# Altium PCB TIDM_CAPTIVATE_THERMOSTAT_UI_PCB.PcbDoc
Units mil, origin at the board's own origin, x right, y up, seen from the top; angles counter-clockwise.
Board outline 2500 x 2500 mil, 2 copper layers (Top Layer, Bottom Layer), stack 62 mil thick; 61 components, 47 nets, 313 pads, 106 vias.
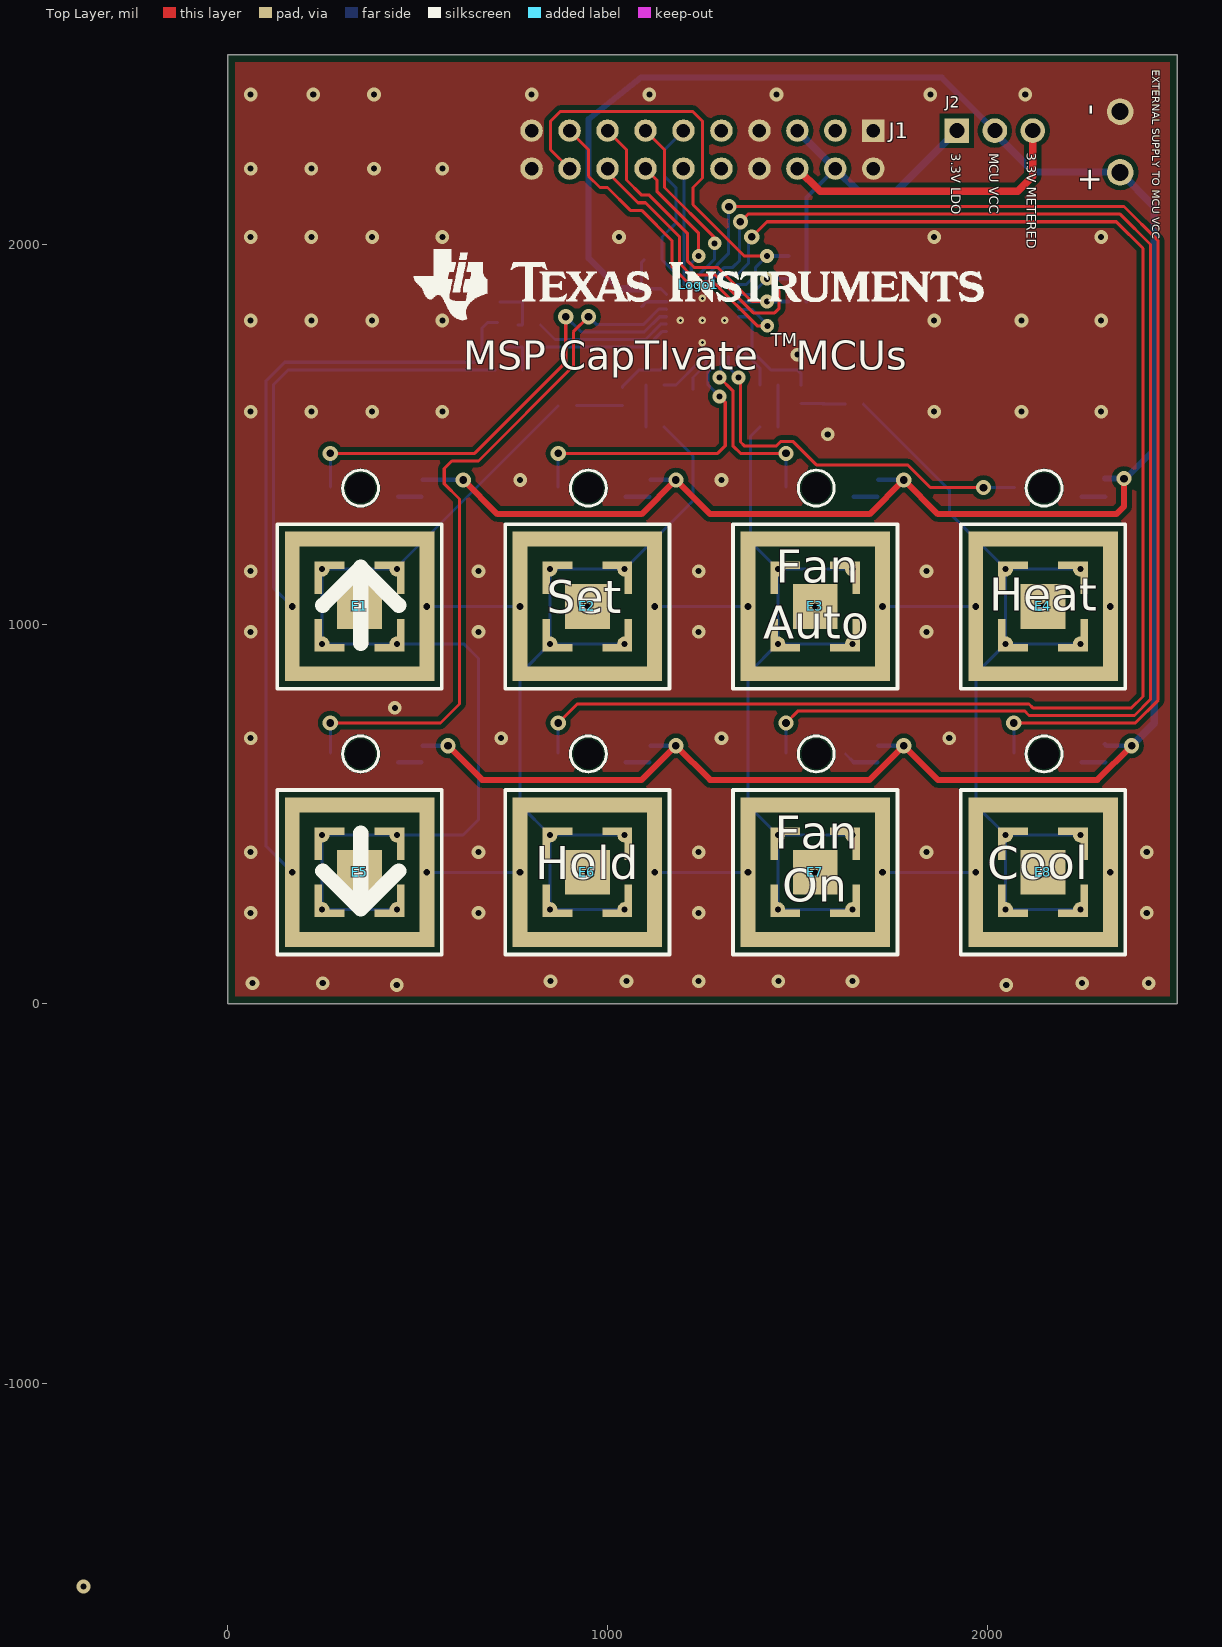
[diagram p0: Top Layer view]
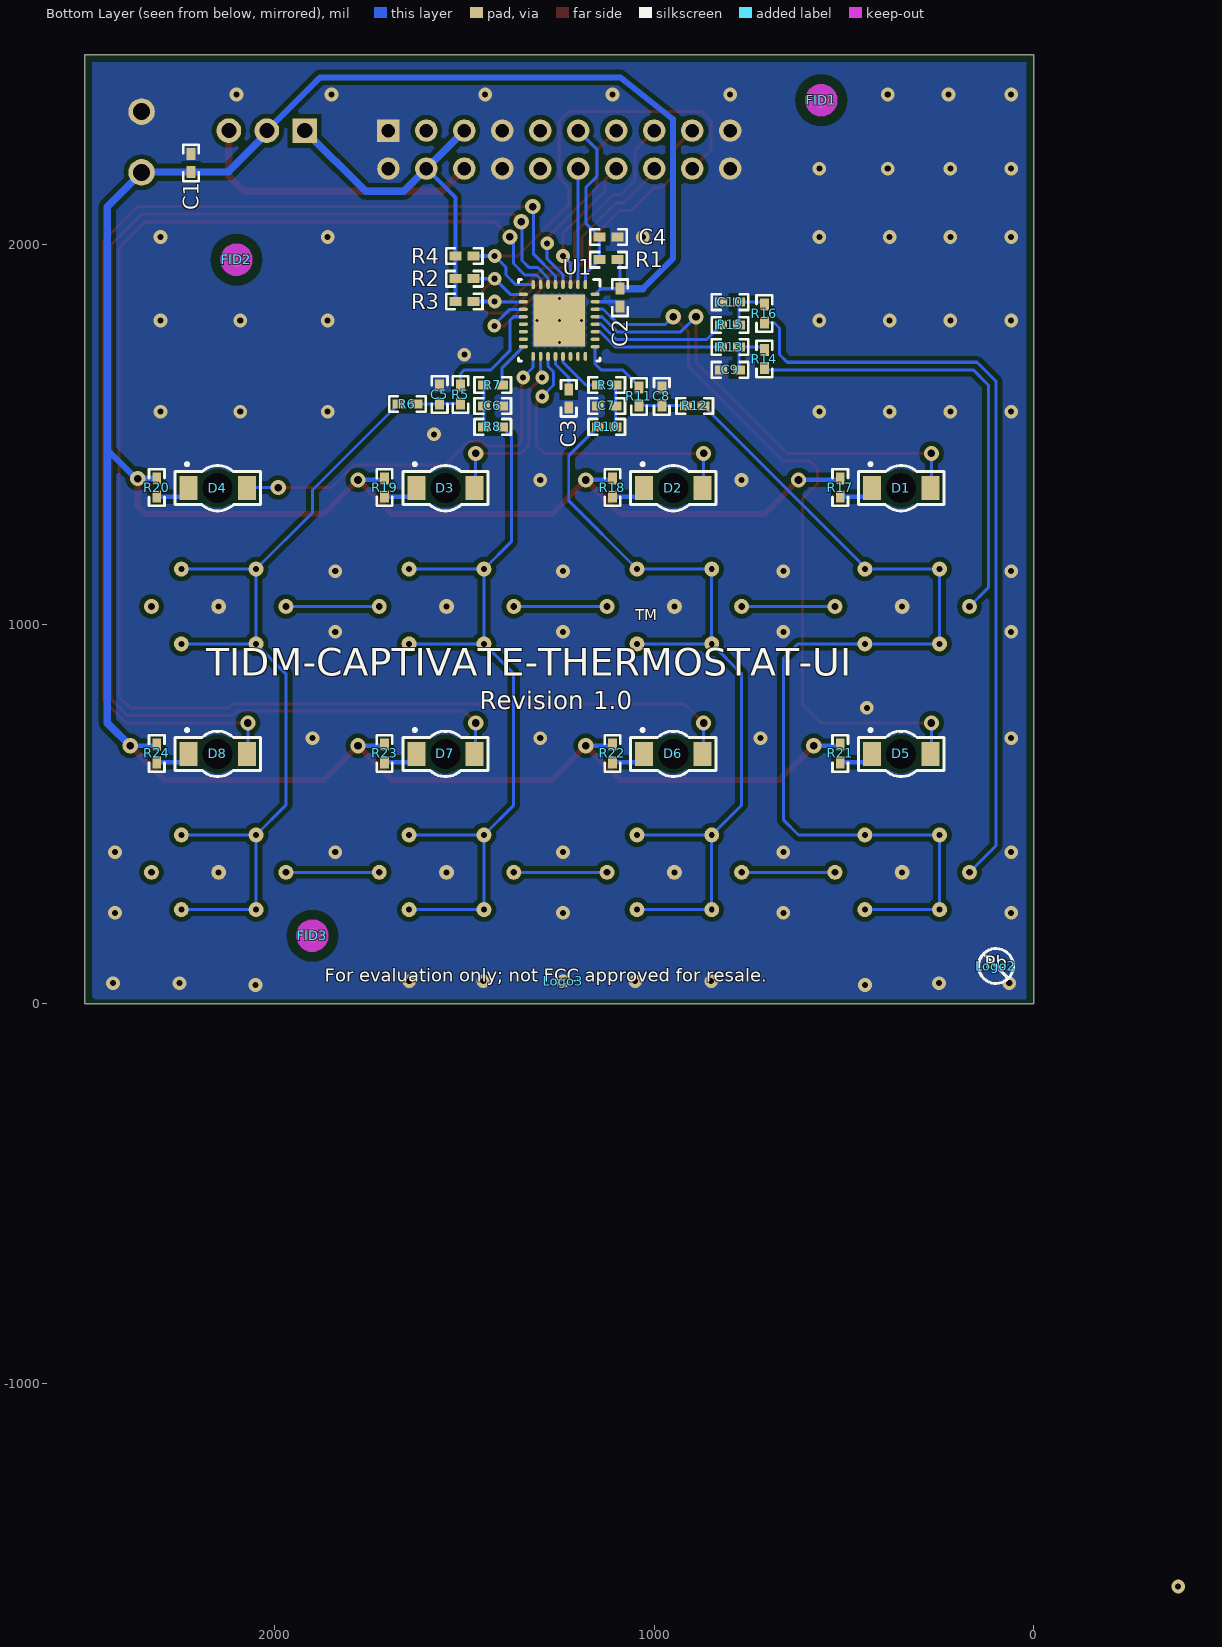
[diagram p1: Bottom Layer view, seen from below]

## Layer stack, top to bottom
Top Solder: solder mask 0.4, Solder Resist, Dk 3.5
Top Layer: signal copper 1.4
Dielectric1: core 59.2, FR-4, Dk 4.8
Bottom Layer: signal copper 1.4
Bottom Solder: solder mask 0.4, Solder Resist, Dk 3.5

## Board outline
0,0 2500,0 2500,2500 0,2500

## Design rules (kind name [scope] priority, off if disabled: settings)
AcuteAngle [All] p1: minimum=4.50000000000000E+0001 checktracksonly=FALSE
AssemblyTestPointUsage [All] p1: valid=2
Clearance Clearance_Keepouts [((IsTrack Or IsArc) And Not InPoly) And IsFree and IsKeepOut vs ((IsTrack Or IsArc) And Not InPoly) And IsFree and IsKeepOut] p1: gap=0
Clearance Clearance_BoardEdge_MountingHoles [OnCopper and InComponentClass('Mounting Holes') vs IsKeepOut] p2: gap=40
Clearance Clearance_BoardEdge_Poly [OnCopper and InPoly vs IsKeepOut] p3: gap=25
Clearance Clearance_BoardEdge [OnCopper and Not InComponentClass('Logo') and not InComponentClass('FiducialMark') and not InRegion(1000,500,4000,800) and Not IsKeepout vs IsKeepOut] p4: gap=75
Clearance Clearance_Poly [InPolygon] p5: gap=12
Clearance [All] p6: gap=7.87
ComponentClearance ComponentClearance_MountingHoles_FiducialMarks [InComponentClass('Mounting Holes') vs InComponentClass('FiducialMark')] p1: gap=50 collisioncheckmode=3 verticalgap=10 showdistances=FALSE
ComponentClearance ComponentClearance_Shunt [InComponentClass('Header') vs InComponentClass('Shunt')] p2: gap=0 collisioncheckmode=3 verticalgap=0 showdistances=FALSE
ComponentClearance ComponentClearance_Logo [InComponentClass('Logo')] p3: gap=50 collisioncheckmode=3 verticalgap=10 showdistances=FALSE
ComponentClearance ComponentClearance_ScrewToNut [(HasFootprint('NY PMS 440 0025 PH')) vs (HasFootprint('Keystone_1902C'))] p4: gap=5 collisioncheckmode=3 verticalgap=10 showdistances=FALSE
ComponentClearance ComponentClearance_MountingHoles [InComponentClass('Mounting Holes')] p5: gap=250 collisioncheckmode=3 verticalgap=100000 showdistances=FALSE
ComponentClearance ComponentClearance_SmallPassives [HasFootprint('0201*') or HasFootprint('0402*') or HasFootprint('0508') or HasFootprint('0603*') or HasFootprint('0612') or HasFootprint('0805*') or HasFootprint('0815*') or HasFootprint('0830*') or HasFootprint('1206*') or HasFootprint('1210*') or HasFootprint('1808*') or HasFootprint('1812*') or HasFootprint('1825*') or HasFootprint('2010*') or HasFootprint('2220*') or HasFootprint('2225*') or HasFootprint('2512*') or HasFootprint('2728*') or HasFootprint('3518*') vs HasFootprint('0201*') or HasFootprint('0402*') or HasFootprint('0508') or HasFootprint('0603*') or HasFootprint('0612') or HasFootprint('0805*') or HasFootprint('0815*') or HasFootprint('0830*') or HasFootprint('1206*') or HasFootprint('1210*') or HasFootprint('1808*') or HasFootprint('1812*') or HasFootprint('1825*') or HasFootprint('2010*') or HasFootprint('2220*') or HasFootprint('2225*') or HasFootprint('2512*') or HasFootprint('2728*') or HasFootprint('3518*')] p6: gap=20 collisioncheckmode=3 verticalgap=10 showdistances=FALSE
ComponentClearance ComponentClearance_THtoSMT [IsThruComponent vs IsSMTComponent] p7: gap=25 collisioncheckmode=3 verticalgap=30 showdistances=FALSE
ComponentClearance ComponentClearance_THtoTH [IsThruComponent vs IsThruComponent] p8: gap=25 collisioncheckmode=3 verticalgap=30 showdistances=FALSE
ComponentClearance [All] p9: gap=40 collisioncheckmode=3 verticalgap=10 showdistances=FALSE
DiffPairsRouting [All] p1: maxlimit=100 minlimit=10 mostfreqgap=10 toplayer_minwidth=15 toplayer_maxwidth=15 toplayer_prefwidth=15 bottomlayer_minwidth=15 bottomlayer_maxwidth=15 bottomlayer_prefwidth=15 maxuncoupledlength=1000
FabricationTestPointUsage TestPointUsage [All] p1: valid=2 allowmultiple=FALSE
FabricationTestpoint Testpoint [All] p1: side=3 testpointundercomponent=TRUE minsize=40 maxsize=100 preferedsize=60 minholesize=0 maxholesize=40 preferedholesize=32 testpointgrid=1 allowsidetop=TRUE allowsidebottom=TRUE usegrid=TRUE gridtolerance=0.01
FanoutControl Fanout_LCC [IsLCC] p1: bgadir=Out bgaviamode=Centered fanoutstyle=Auto fanoutdirection=Alternating viagrid=1 // Fanout_LCC (Default Rule)
FanoutControl Fanout_BGA [IsBGA] p2: bgadir=Out bgaviamode=Centered fanoutstyle=Auto fanoutdirection=Alternating viagrid=1 // Fanout_BGA (Default Rule)
FanoutControl Fanout_Default [All] p4: bgadir=Out bgaviamode=Centered fanoutstyle=Auto fanoutdirection=Alternating viagrid=1 // Fanout_Default (Default Rule)
FanoutControl Fanout_Small [(CompPinCount < 5)] p5: bgadir=Out bgaviamode=Centered fanoutstyle=Auto fanoutdirection=OutThenIn viagrid=1 // Fanout_Small (Default Rule)
HoleSize [All] p1: absolutevalues=TRUE maxlimit=251 minlimit=8 maxpercent=80.000 minpercent=20.000
MinimumAnnularRing MinimumAnnularRing_ThermalPadVias [IsVia and InAnyComponent] p1: minimumring=5.91
MinimumAnnularRing [All] p2: minimumring=9
MinimumSolderMaskSliver MinimumSolderMaskSliver_Logo [InComponentClass('Logo') vs InComponentClass('Logo')] p1: minsoldermaskwidth=0.7
MinimumSolderMaskSliver [All] p2: minsoldermaskwidth=3.94
PlaneConnect [All] p1: planeconnectstyle=Direct reliefexpansion=10 reliefentries=4 reliefconductorwidth=10 reliefairgap=10
PolygonConnect [All] p1: connectstyle=Direct reliefconductorwidth=10 reliefentries=4 polygonreliefangle="90 Angle" airgapwidth=10
RoutingVias ThermalPadVias [IsVia and InAnyComponent] p1: holewidth=7.87 width=19.68 viastyle="Through Hole" minholewidth=7.87 minwidth=19.68 maxholewidth=12.99 maxwidth=23.62
RoutingVias [All] p2: holewidth=16 width=34 viastyle="Through Hole" minholewidth=7.87 minwidth=26 maxholewidth=40 maxwidth=65
SilkToBoardRegionClearance [Not ((IsComment or IsDesignator) And (Hide <> 'False')) and not InRegion(1000,500,4000,800)] p1:
SilkToSilkClearance SilkToSilkClearance_Pb-FreeLogo [(HasFootprint('Pb-Free_Overlay_Medium') OR HasFootprint('Pb-Free_Overlay_Small')) vs (HasFootprint('Pb-Free_Overlay_Medium') OR HasFootprint('Pb-Free_Overlay_Small'))] p1: silktosilkclearance=0
SilkToSilkClearance [All] p2: silktosilkclearance=5
SilkToSolderMaskClearance "Silk to Solder Mask Opening" [All] p1: minsilkscreentomaskgap=1 clearancetoexposedcopper=FALSE
SolderMaskExpansion [All] p1: expansion=1.97
UnpouredPolygon [All] p1: allowunpoured=FALSE
Width [All] p1: maxlimit=100 minlimit=6 preferedwidth=10 checkconnectedcopper=TRUE
14 further rules are at their usual default settings.

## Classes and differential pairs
component class Logo: Logo1
component class TIDM_CAPTIVATE_THERMOSTAT_UI_Circuit: + - C2 C3 C4 C5 C6 C7 C8 C9 C10 D1 D2 D3 D4 D5 D6 D7 D8 E1 E2 E3 E4 E5 E6 E7 E8 J1 R1 R2 R3 R4 R5 R6 R7 R8 R9 R10 R11 R12 R13 R14 R15 R16 R17 R18 R19 R20 R21 R22 R23 R24 U1
component class TIDM_CAPTIVATE_THERMOSTAT_UI_Hardware: FID1 FID2 FID3 Logo1 Logo2 Logo3
component class FiducialMark: FID1 FID2 FID3

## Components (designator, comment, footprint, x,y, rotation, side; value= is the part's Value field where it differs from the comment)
+ "VCC_MSP" Mill-Max_2505-2 2350,2190 r90 top (schematic designator TP2)
- "GND" Mill-Max_2505-2 2350,2350 r90 top (schematic designator TP1)
C1 "C1005X5R0J475M050BC" 0402 2220,2215 r90 bottom
C2 "C1005X5R0J104K" 0402 1090,1860 r270 bottom
C3 "C1005X5R0J105M" 0402 1225,1595 r270 bottom
C4 "GRM1555C1E511JA01D" 0402 1120,2020 r180 bottom
C5 "GRM1555C1H680JA01D" 0402 1565,1605 r90 bottom
C6 "GRM1555C1H680JA01D" 0402 1425,1575 r180 bottom
C7 "GRM1555C1H680JA01D" 0402 1125,1575 r0 bottom
C8 "GRM1555C1H680JA01D" 0402 980,1600 r90 bottom
C9 "GRM1555C1H680JA01D" 0402 800,1670 r0 bottom
C10 "GRM1555C1H680JA01D" 0402 800,1848.21 r0 bottom
D1 "Green LED" 1206_ReverseMount_LED 450,1390 r180 top
D2 "Green LED" 1206_ReverseMount_LED 1050,1390 r180 top
D3 "Green LED" 1206_ReverseMount_LED 1650,1390 r180 top
D4 "Green LED" 1206_ReverseMount_LED 2250,1390 r180 top
D5 "Green LED" 1206_ReverseMount_LED 450,690 r180 top
D6 "Green LED" 1206_ReverseMount_LED 1050,690 r180 top
D7 "Green LED" 1206_ReverseMount_LED 1650,690 r180 top
D8 "Green LED" 1206_ReverseMount_LED 2250,690 r180 top
E1 "Btn-Mutual-EMC" electrode-mutual-highemc-cut-rotated 150,850 r0 top
E2 "Btn-Mutual-EMC" electrode-mutual-highemc-cut-rotated 750,850 r0 top
E3 "Btn-Mutual-EMC" electrode-mutual-highemc-cut-rotated 1350,850 r0 top
E4 "Btn-Mutual-EMC" electrode-mutual-highemc-cut-rotated 1950,850 r0 top
E5 "Btn-Mutual-EMC" electrode-mutual-highemc-cut-rotated 150,150 r0 top
E6 "Btn-Mutual-EMC" electrode-mutual-highemc-cut-rotated 750,150 r0 top
E7 "Btn-Mutual-EMC" electrode-mutual-highemc-cut-rotated 1350,150 r0 top
E8 "Btn-Mutual-EMC" electrode-mutual-highemc-cut-rotated 1950,150 r0 top
FID1 "Fiducial" Fiducial10-20 560,2380 r180 bottom
FID2 "Fiducial" Fiducial10-20 2100,1960 r180 bottom
FID3 "Fiducial" Fiducial10-20 1900,180 r180 bottom
J1 "Connector 10X2RA" CONN2X10RA 1700,2300 r180 top
J2 "TSW-103-07-G-S" TSW-103-07-G-S 2020,2300 r0 top
Logo1 "Texas Instruments" TI_Horizontal_Overlay_Medium 1240.16,1894.49 r0 top
Logo2 "Pb-Free Symbol" Pb-Free_Overlay_Small 100,100 r180 bottom
Logo3 "FCC disclaimer" FCC_disclaimer 1240,60 r180 bottom
R1 "CRCW040247K0JNED" 0402 1120,1960 r180 bottom
R2 "CRCW04024K70JNED" 0402 1500,1910 r180 bottom
R3 "CRCW04024K70JNED" 0402 1500,1850 r180 bottom
R4 "CRCW04024K70JNED" 0402 1500,1970 r180 bottom
R5 "CRCW0402470RJNED" 0402 1510,1605 r270 bottom
R6 "CRCW0402470RJNED" 0402 1650,1580 r0 bottom
R7 "CRCW0402470RJNED" 0402 1425,1630 r0 bottom
R8 "CRCW0402470RJNED" 0402 1425,1520 r180 bottom
R9 "CRCW0402470RJNED" 0402 1125,1630 r180 bottom
R10 "CRCW0402470RJNED" 0402 1125,1520 r0 bottom
R11 "CRCW0402470RJNED" 0402 1040,1600 r270 bottom
R12 "CRCW0402470RJNED" 0402 893.19,1575 r180 bottom
R13 "CRCW0402470RJNED" 0402 800,1730 r180 bottom
R14 "CRCW0402470RJNED" 0402 710,1698.21 r270 bottom
R15 "CRCW0402470RJNED" 0402 800,1788.21 r180 bottom
R16 "CRCW0402470RJNED" 0402 710,1818.21 r270 bottom
R17 "CRCW0402510RJNED" 0402 510,1360 r270 bottom
R18 "CRCW0402510RJNED" 0402 1110,1360 r270 bottom
R19 "CRCW0402510RJNED" 0402 1710,1360 r270 bottom
R20 "CRCW0402510RJNED" 0402 2310,1360 r270 bottom
R21 "CRCW0402510RJNED" 0402 510,660 r270 bottom
R22 "CRCW0402510RJNED" 0402 1110,660 r270 bottom
R23 "CRCW0402510RJNED" 0402 1710,660 r270 bottom
R24 "CRCW0402510RJNED" 0402 2310,660 r270 bottom
U1 "MSP430FR2633IRHB" RHB0032E 1250,1800 r270 bottom

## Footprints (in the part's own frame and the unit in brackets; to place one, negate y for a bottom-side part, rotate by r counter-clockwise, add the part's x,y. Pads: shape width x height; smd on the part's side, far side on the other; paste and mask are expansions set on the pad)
0402 [mm] "0402 from SM-752 data"
  rect 0.8x0.6 smd: 1(-0.6,0) 2(0.6,0)
  silkscreen extent -1.22,-0.52 1.22,0.52, body extent -0.55,-0.3 0.55,0.3, height 0.6
1206_ReverseMount_LED [mm]
  rect 1.2x1.6 smd far side: 1(0.6,0.8) 2(4.5,0.8)
  round 0 hole 2 unplated: ""(2.55,0.8)
  silkscreen extent 1.35,-0.4 3.75,2
CONN2X10RA [mm] "Connector;F-Receptacle; 10x2 Position; Right Angle"
  rect 1.5x1.5 hole 0.9: 1(0,0)
  round 1.5 hole 0.9: 2(0,2.54) 3(2.54,0) 4(2.54,2.54) 5(5.08,0) 6(5.08,2.54) 7(7.62,0) 8(7.62,2.54) 9(10.16,0) 10(10.16,2.54) 11(12.7,0) 12(12.7,2.54) 13(15.24,0) 14(15.24,2.54) 15(17.78,0) 16(17.78,2.54) 17(20.32,0) 18(20.32,2.54) 19(22.86,0) 20(22.86,2.54)
  body extent -1.52,-10.03 24.38,-1.52, height 4.95
electrode-mutual-highemc-cut-rotated [mm] "Mutual Capacitance Sensing Electrode with High EMC and Cut Rx Square, Rotated"
  rect 3x3 smd paste+0: GND(5,5)
  round 1 hole 0.4: GND(5,5) RX(2.5,2.5) RX(2.5,7.5) RX(7.5,2.5) RX(7.5,7.5)
  rect 0.5x1.667 smd paste+0: RX(2.25,3.333) RX(2.25,6.667) RX(7.75,3.333) RX(7.75,6.667)
  rect 2x0.5 smd paste+0: RX(3,2.25) RX(3,7.75) RX(7,2.25) RX(7,7.75)
  rect 1x10 smd paste+0: TX(0.5,5) TX(9.5,5)
  round 1 hole 0.45: TX(0.5,5) TX(9.5,5)
  rect 10x1 smd paste+0: TX(5,0.5) TX(5,9.5)
  Bottom Layer lines w0.2: 7.5,2.5 2.5,2.5 2.5,7.5 7.5,7.5
  silkscreen extent -0.5,-0.5 10.5,10.5
FCC_disclaimer [mil]
Fiducial10-20 [mm]
  round 1 smd mask+0.5: 1(0,0)
  Top Layer keep-out circle w1.178: c0,0 r0.5
Mill-Max_2505-2 [mil] "Mill-Max"
  round 70 hole 45 paste+0: 1(0,0)
  body extent -62,-63 62,62, height 187
Pb-Free_Overlay_Small [mil]
  silkscreen extent -46,-46 46,46
RHB0032E [mm] "QFN, 32-Leads, Body 5x5mm, Pitch 0.5mm, Thermal Pad 3.45x3.45mm, TI Recommended"
  oval 0.6x0.24 smd: 1(-2.4,1.75) 2(-2.4,1.25) 3(-2.4,0.75) 4(-2.4,0.25) 5(-2.4,-0.25) 6(-2.4,-0.75) 7(-2.4,-1.25) 8(-2.4,-1.75) 17(2.4,-1.75) 18(2.4,-1.25) 19(2.4,-0.75) 20(2.4,-0.25) 21(2.4,0.25) 22(2.4,0.75) 23(2.4,1.25) 24(2.4,1.75)
  oval 0.24x0.6 smd: 9(-1.75,-2.4) 10(-1.25,-2.4) 11(-0.75,-2.4) 12(-0.25,-2.4) 13(0.25,-2.4) 14(0.75,-2.4) 15(1.25,-2.4) 16(1.75,-2.4) 25(1.75,2.4) 26(1.25,2.4) 27(0.75,2.4) 28(0.25,2.4) 29(-0.25,2.4) 30(-0.75,2.4) 31(-1.25,2.4) 32(-1.75,2.4)
  rect 3.45x3.45 smd paste-1.725: 33(0,0)
  silkscreen extent -2.72,-2.73 2.72,2.73, body extent -2.57,-2.57 2.58,2.58, height 1.01
TI_Horizontal_Overlay_Medium [mil]
  silkscreen extent -750,-94 750,94
TSW-103-07-G-S [mm] "Samtec 100mil, 1x3, 230 mil above insulator"
  rect 1.65x1.65 hole 1.016: 1(-2.54,0)
  round 1.65 hole 1.016: 2(0,0) 3(2.54,0)
  body extent -3.81,-1.27 3.81,1.27, height 8.38

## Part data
+ -: library part 2505-2-00-44-00-00-07-0, "PCB Pin, Swage Mount, TH"
C1: "CAP, CERM, 4.7 µF, 6.3 V, +/- 20%, X5R, 0402"
C2: "CAP, CERM, 0.1 µF, 6.3 V, +/- 10%, X5R, 0402"
C3: "CAP, CERM, 1 µF, 6.3 V, +/- 20%, X5R, 0402"
C4: "CAP, CERM, 510 pF, 25 V, +/- 5%, C0G/NP0, 0402"
C5 C6 C7 C8 C9 C10: "CAP, CERM, 68 pF, 50 V, +/- 5%, C0G/NP0, 0402"
D1 D2 D3 D4 D5 D6 D7 D8: library part 597-6301-607F, "LED, Green, SMD, Reverse Mount, 1206"
E1 E2 E3 E4 E5 E6 E7 E8: library part btn-mutual-emc, "Capacitive Button, Mutual, 2-layer, High EMC"
FID1 FID2 FID3: "Fiducial mark.  There is nothing to buy or mount."
J1: "Connector, Female, 10-Pin, 2 row, Right Angle"
J2: "Header, 100mil, 3x1, Gold, TH"
Logo1: library part TI_Logo, "Texas Instrument Corporate Signature"
Logo2: library part Pb-Free
Logo3: library part FCC_disclaimer, "FCC_disclaimer"
R1: "RES, 47 k, 5%, 0.063 W, 0402"
R2 R3 R4: "RES, 4.7 k, 5%, 0.063 W, 0402"
R5 R6 R7 R8 R9 R10 R11 R12 R13 R14 R15 R16: "RES, 470, 5%, 0.063 W, 0402"
R17 R18 R19 R20 R21 R22 R23 R24: "RES, 510, 5%, 0.063 W, 0402"
U1: "MSP430 Captivate Microcontroller"

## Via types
v1: diameter 36, hole 16, Top Layer to Bottom Layer, tented both sides, 80 vias
v2: diameter 40, hole 20, Top Layer to Bottom Layer, tented both sides, 21 vias
v3: diameter 19.68, hole 7.87, Top Layer to Bottom Layer, tented both sides, 5 vias

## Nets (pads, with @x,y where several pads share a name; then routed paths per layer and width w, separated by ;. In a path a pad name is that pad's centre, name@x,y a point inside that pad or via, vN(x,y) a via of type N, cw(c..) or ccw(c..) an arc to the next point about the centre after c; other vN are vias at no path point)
GND: -.1 C1.2 C2.2 C3.2 C4.2 C5.2 C6.2 C7.2 C8.2 C9.2 C10.2 E1.GND E2.GND E3.GND E4.GND E5.GND E6.GND E7.GND E8.GND J1.1 J1.2 J1.7 J1.8 J1.19 J1.20 U1.31 U1.33 | length 70.8
  Bottom Layer w8: C2.2 1102.83,1849.21
  Bottom Layer w9: 1102.83,1849.21 U1.31
  other v1: 445,50 2050,50 65,55 250,55 2250,55 2425,55 850,60 1050,60 1240,60 1450,60 1645,60 60,240 660,240 1240,240 2420,240 60,400 660,400 1240,400 1840,400 2420,400 60,700 720,700 1300,700 1900,700 440,780 60,980 660,980 1240,980 1840,980 60,1140 660,1140 1240,1140 1840,1140 770,1380 1300,1380 1580,1500 60,1560 220,1560 380,1560 565,1560 1860,1560 2090,1560 2300,1560 1500,1710 60,1800 220,1800 380,1800 565,1800 1860,1800 2090,1800 2300,1800 60,2020 220,2020 380,2020 565,2020 1030,2020 1860,2020 2300,2020 60,2200 220,2200 385,2200 565,2200 60,2395 225,2395 385,2395 800,2395 1110,2395 1445,2395 1850,2395 2100,2395
  other v3: 1250,1741.93 1191.93,1800 1250,1800 1308.07,1800 1250,1858.07
IRQ: J1.18 R4.2 U1.8 | length 1248.2
  Top Layer w8: J1.18 850,2250 850,2325 875,2350 1225,2350 1250,2325 1250,2175 1225,2150 1225,2105 1360,1970 v1(1420,1970)
  Bottom Layer w8: U1.8 1364.49,1894.49 1390,1920 1390,1940 v1(1420,1970)
  Bottom Layer w10: v1(1420,1970) R4.2
LED1: D1.2 U1.29 | length 1226.7
  Top Layer w8: v2(270,1450) 650,1450 890,1690 v2(890,1810)
  Bottom Layer w8: D1.2@270,1361.34 v2(270,1450) ; v2(890,1810) 930,1770 1097.45,1770 1137.29,1809.84 U1.29
LED2: D2.2 U1.19 | length 797.1
  Top Layer w8: v2(870,1450) 1290,1450 1310,1470 1310,1585 v1(1295,1600)
  Bottom Layer w8: D2.2@870,1361.34 v2(870,1450) ; U1.19 1279.53,1679.53 1265,1665 1265,1630 v1(1295,1600)
LED3: D3.2 U1.18 | length 488.7
  Top Layer w8: v1(1295,1650) 1330,1615 1330,1470 1350,1450 v2(1470,1450)
  Bottom Layer w8: v1(1295,1650) 1299.21,1654.21 U1.18 ; D3.2@1470,1361.34 v2(1470,1450)
LED4: D4.2 U1.17 | length 1019.3
  Top Layer w8: v1(1345,1650) 1350,1645 1350,1480 1360,1470 1444.92,1470 1456.8,1481.87 1488.13,1481.87 1550,1420 1790,1420 1850,1360 v2(1990,1360)
  Bottom Layer w8: U1.17 1318.9,1676.1 v1(1345,1650) ; v2(1990,1360) D4.2@2071.34,1360
LED5: D5.2 U1.30 | length 1904.9
  Top Layer w8: v2(270,740) 560,740 610,790 610,1330 570,1370 570,1410 590,1430 660,1430 910,1680 910,1770 v2(950,1810)
  Bottom Layer w8: D5.2@270,661.34 v2(270,740) ; v2(950,1810) 970,1790 1095,1790 1135,1830 1155.04,1830 U1.30
LED6: D6.2 U1.7 | length 4088.5
  Top Layer w8: v2(870,740) 920,790 2110,790 2120,780 2380,780 2410,810 2410,1990 2340,2060 1420,2060 v2(1380,2020)
  Bottom Layer w8: D6.2@870,661.34 v2(870,740) ; U1.7 1299.21,1909.21 1310,1920 1340.72,1920 1370.72,1950 1370.72,2010.72 v2(1380,2020)
LED7: D7.2 U1.6 | length 3601.2
  Top Layer w8: v2(1350,2060) 1370,2080 2350,2080 2430,2000 2430,802.45 2387.55,760 2110,760 2098.13,771.87 1501.87,771.87 v2(1470,740)
  Bottom Layer w8: U1.6 1279.53,1911.98 1307.55,1940 1330,1940 1348.13,1958.13 1348.13,2058.13 v2(1350,2060) ; D7.2@1470,661.34 v2(1470,740)
LED8: D8.2 U1.5 | length 3091.2
  Top Layer w8: v2(1320,2100) 2360,2100 2450,2010 2450,800 2390,740 v2(2070,740)
  Bottom Layer w8: U1.5 1259.84,1917.39 1318.13,1975.68 1318.13,2098.13 v2(1320,2100) ; D8.2@2070,661.34 v2(2070,740)
NetC5_1: C5.1 R5.2 R6.1 | length 121.4
  Bottom Layer w7.87: R5.2 C5.1 C5.1@1571.38,1581.38 ; C5.1@1566.38,1580 R6.1
NetC6_1: C6.1 R7.2 R8.1 | length 110
  Bottom Layer w7.87: R8.1 R7.2
NetC7_1: C7.1 R9.2 R10.1 | length 110
  Bottom Layer w7.87: R10.1 R9.2
NetC8_1: C8.1 R11.2 R12.1 | length 121.8
  Bottom Layer w8: R12.1@918.19,1576.38 C8.1 R11.2
NetC9_1: C9.1 R13.2 R14.1 | length 118.2
  Bottom Layer w8: R14.1@718.17,1730 R13.2 C9.1
NetC10_1: C10.1 R15.2 R16.1 | length 132.8
  Bottom Layer w8: R16.1@716.38,1848.21 C10.1 R15.2 R15.2@763.62,1788.21
NetD1_1: D1.1 R17.2 | length 61.5
  Bottom Layer w12: D1.1@448.5,1336.38 R17.2
NetD2_1: D2.1 R18.2 | length 61.5
  Bottom Layer w12: D2.1@1048.5,1336.38 R18.2
NetD3_1: D3.1 R19.2 | length 61.5
  Bottom Layer w12: D3.1@1648.5,1336.38 R19.2
NetD4_1: D4.1 R20.2 | length 61.5
  Bottom Layer w12: D4.1@2248.5,1336.38 R20.2
NetD5_1: D5.1 R21.2 | length 61.5
  Bottom Layer w12: D5.1@448.5,636.38 R21.2
NetD6_1: D6.1 R22.2 | length 61.5
  Bottom Layer w12: D6.1@1048.5,636.38 R22.2
NetD7_1: D7.1 R23.2 | length 92.8
  Bottom Layer w7.87: D7.1 D7.1@1648.5,636.38
  Bottom Layer w12: D7.1@1648.5,636.38 R23.2
NetD8_1: D8.1 R24.2 | length 61.5
  Bottom Layer w12: D8.1@2248.5,636.38 R24.2
NetR5_1: R5.1 U1.12 | length 305.8
  Bottom Layer w8: U1.12 1370.16,1809.84 1380,1800 1380,1720 1430,1670 1500,1670 1510,1660 R5.1
NetR7_1: R7.1 U1.16 | length 124.7
  Bottom Layer w7.87: U1.16 1401.38,1674.21 R7.1
NetR9_1: R9.1 U1.21 | length 131.9
  Bottom Layer w7.87: R9.1 1180.16,1630 1240.16,1690 U1.21
NetR11_1: R11.1 U1.25 | length 188.6
  Bottom Layer w8: R11.1 1040,1626.81 1083.19,1670 1140,1670 1155.51,1685.51 U1.25
NetR13_1: R13.1 U1.27 | length 348.7
  Bottom Layer w8: R13.1 1102.45,1730 1142.92,1770.47 U1.27
NetR15_1: R15.1 U1.28 | length 364.4
  Bottom Layer w8: R15.1 861.83,1750 1100,1750 1140.16,1790.16 U1.28
RST: C4.1 J1.11 R1.1 U1.1 | length 469.2
  Bottom Layer w8: U1.1 1181.1,1922.52 R1.1 C4.1 1180,2056.38 1180,2150 1150,2180 1150,2250 J1.11
RX0: E4.RX E8.RX R6.2 | length 1158.1
  Bottom Layer w7.87: R6.2 1900,1353.62 1900,1293.7 E4.RX@2048.43,1145.28 ; E8.RX@2048.43,445.28 1970,523.7 1970,870 E4.RX@2048.43,948.43
RX1: E3.RX E7.RX R8.2 | length 983
  Bottom Layer w7.87: R8.2 1376.38,1495 1376.38,1217.32 E3.RX@1448.43,1145.28 ; E7.RX@1448.43,445.28 1370,523.7 1370,870 E3.RX@1448.43,948.43
RX2: E2.RX E6.RX R10.2 | length 1048.9
  Bottom Layer w7.87: E6.RX@848.43,445.28 770,523.7 770,870 E2.RX@848.43,948.43 ; E2.RX@1045.28,1145.28 1225,1325 1225,1443.62 R10.2
RX3: E1.RX E5.RX R12.2 | length 1486.7
  Bottom Layer w7.87: E5.RX@445.28,445.28 620,445.28 660,485.28 660,910 621.57,948.43 E1.RX@445.28,948.43 ; E1.RX@445.28,1150.71 R12.2
RXD: J1.13 U1.4 | length 498.2
  Top Layer w8: J1.13 1150,2250 1150,2150 1282,2018 v1(1282,2003)
  Bottom Layer w8: U1.4 1240.16,1920.16 1282,1962 v1(1282,2003)
SCL: J1.15 R3.2 U1.10 | length 826.7
  Top Layer w8: J1.15 1050,2250 1050,2170 1090,2130 1110,2130 1210.13,2029.87 1210.13,1957.63 1227.63,1940.13 1229,1940.13 1230,1939.13 1290.87,1939.13 1380,1850 v1(1420,1850)
  Bottom Layer w8: U1.10 v1@1419.21,1849.21
  Bottom Layer w10: v1(1420,1850) R3.2
SDA: J1.16 R2.2 U1.9 | length 901.4
  Top Layer w8: J1.16 1000,2190 1080,2110 1100,2110 1190,2020 1190,1950 1220,1920 1283.83,1920 1383.83,1820 1440,1820 1452,1832 1452,1878 v1(1420,1910)
  Bottom Layer w8: U1.9 1378.9,1868.9 v1(1420,1910)
  Bottom Layer w10: v1(1420,1910) R2.2
SYNC: J1.17 U1.11 | length 908.8
  Top Layer w8: J1.17 950,2250 950,2180 980,2150 1000,2150 1060,2090 1090,2090 1170,2010 1170,1941.38 1210,1901.38 1280,1901.38 1280,1900 1394.21,1785.79 v1(1420.79,1785.79)
  Bottom Layer w8: U1.11 1380.47,1829.53 v1@1420.79,1789.21
TEST: J1.12 U1.2 | length 304.7
  Bottom Layer w8: U1.2 J1.12@1200.79,2199.21
TX0: E1.TX E2.TX E3.TX E4.TX R14.2 | length 1942.7
  Bottom Layer w8: E1.TX@169.68,1046.85 120,1096.54 120,1630 160,1670 R14.2@705.41,1670 ; E1.TX@524.02,1046.85 E2.TX@769.68,1046.85 ; E2.TX@1124.02,1046.85 E3.TX@1369.68,1046.85 ; E3.TX@1724.02,1046.85 E4.TX@1969.68,1046.85
TX1: E5.TX E6.TX E7.TX E8.TX R16.2 | length 2773.8
  Bottom Layer w8: E5.TX@169.68,346.85 100,416.54 100,1640 150,1690 649.54,1690 670,1710.46 670,1780 684.59,1794.59 R16.2 ; E5.TX@524.02,346.85 E6.TX@769.68,346.85 ; E6.TX@1124.02,346.85 E7.TX@1369.68,346.85 ; E7.TX@1724.02,346.85 E8.TX@1969.68,346.85
TXD: J1.14 U1.3 | length 371.6
  Top Layer w8: J1.14 1130,2170 1130,2140 1240,2030 v1(1240,1970)
  Bottom Layer w8: U1.3 1220.47,1950.47 v1(1240,1970)
VCC_LDO: J1.4 J1.5 J2.1 R2.1 R3.1 R4.1 | length 934.2
  Bottom Layer w10: R3.1 R2.1 R4.1 1523.62,2123.62 J1.4
  Bottom Layer w20: J1.5 J1.4 1660,2140 1760,2140 J2.1
VCC_METERED: J1.6 J2.3 | length 781.4
  Top Layer w20: J1.6 1560,2140 2080,2140 2120,2180 J2.3
VCC_MSP: +.1 C1.1 C2.1 J2.2 R1.2 R17.1 R18.1 R19.1 R20.1 R21.1 R22.1 R23.1 R24.1 U1.32 | length 8503.1
  Top Layer w16: v2(580,680) 670,590 1090,590 v2(1180,680) 1270,590 1690,590 v2(1780,680) 1870,590 2290,590 v2(2380,680) ; v2(620,1380) 710,1290 1090,1290 v2(1180,1380) 1270,1290 1690,1290 v2(1780,1380) 1870,1290 2340,1290 2360,1310 v2(2360,1383.62)
  Bottom Layer w8: C2.1 1090,1953.62 R1.2 ; 1140.79,1883.62 U1.32
  Bottom Layer w9: C2.1 1140.79,1883.62
  Bottom Layer w12: R21.1@513.62,680 v2(580,680) ; R17.1@513.62,1380 v2(620,1380) ; R22.1@1113.62,680 v2(1180,680) ; R18.1@1113.62,1380 v2(1180,1380) ; R23.1@1713.62,680 v2(1780,680) ; R19.1@1713.62,1380 v2(1780,1380) ; R24.1 2313.62,680 v2(2380,680)
  Bottom Layer w16: 1030,1883.62 950,1963.62 950,2330 1088.45,2439.61 1880.39,2439.61 J2.2 ; R20.1 v2(2360,1383.62) 2363.62,1383.62 2440,1460
  Bottom Layer w20: 1030,1883.62 C2.1 ; J2.2@2020,2293.62 2120,2193.62 ; 2120,2191.63 +.1 2440,2100 2440,1460 2440,740 v2(2380,680)
VREG: C3.1 U1.20 | length 101.3
  Bottom Layer w8: C3.1 1225,1650 1259.84,1684.84 U1.20
pads on no net: D1. D2. D3. D4. D5. D6. D7. D8. FID1.1 FID2.1 FID3.1 J1.3 J1.9 J1.10 U1.13 U1.14 U1.15 U1.22 U1.23 U1.24 U1.26
copper on no net:
  other v1: -380,-1534

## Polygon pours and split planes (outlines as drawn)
GND on Top Layer "Top Layer Ground Plane" (solid, remove dead copper, pour order 3): 20,2480 2480,2480 2480,20 20,20 20,2480
GND on Bottom Layer "Bottom Layer Ground Plane" (solid, remove dead copper, pour order 4): 20,2480 2480,2480 2480,12.46 20,12.46

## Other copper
Top Layer:
  pour cut-out: 2363.39,130.32 1930.32,130.32 1930.32,563.39 2363.39,563.39
  pour cut-out: 1763.39,130.32 1330.32,130.32 1330.32,563.39 1763.39,563.39
  pour cut-out: 1163.39,130.32 730.32,130.32 730.32,563.39 1163.39,563.39
  pour cut-out: 563.39,130.32 130.32,130.32 130.32,563.39 563.39,563.39
  pour cut-out: 563.39,830.32 130.32,830.32 130.32,1263.39 563.39,1263.39
  pour cut-out: 1163.39,830.32 730.32,830.32 730.32,1263.39 1163.39,1263.39
  pour cut-out: 1763.39,830.32 1330.32,830.32 1330.32,1263.39 1763.39,1263.39
  pour cut-out: 2363.39,830.32 1930.32,830.32 1930.32,1263.39 2363.39,1263.39

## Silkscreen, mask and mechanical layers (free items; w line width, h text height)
Top Overlay:
  lines w40: 250,350 350,250 ; 250,1050 350,1150 ; 350,450 350,250 ; 350,950 350,1150 ; 450,350 350,250 ; 450,1050 350,1150
  text "EXTERNAL SUPPLY TO MCU VCC" at 2435,2460 h20 r270
  text "3.3V METERED" at 2103.54,2241.8 h25 r270
  text "3.3V LDO" at 1905,2240 h25 r270
  text "MCU VCC" at 2005,2240 h25 r270
  text "TM" at 1430,1720 h60
  text "MSP CapTIvate   MCUs" at 620,1645 h130
  text "Fan" at 1442.84,1080.58 h150
  text "Heat" at 2005,1006.53 h150
  text "Set" at 840,1000 h150
  text "Auto" at 1409.47,932.45 h150
  text "Fan" at 1440,380 h150
  text "Hold" at 810,300 h150
  text "Cool" at 2000,300 h150
  text "On" at 1460,240 h150
Bottom Overlay:
  text "TM" at 1050,1000 h50
  text "TIDM-CAPTIVATE-THERMOSTAT-UI" at 2180,840 h125
  text "1.0" at 1160,760 h80
  text "Revision" at 1460,760 h80
M1 Board Outline:
  the board outline again, w7.87
M9 Title Sheet:
  drawing of 56 lines, arcs and shapes, not listed
  text "1" at 739.84,8036.5 h70
  text "2" at 3235.5,8036.5 h70
  text "3" at 5724.84,8036.5 h70
  text "4" at 8231.51,8036.5 h70
  text "5" at 10730.5,8036.5 h70
  text "6" at 13235.5,8036.5 h70
  text "A" at -416.5,6893.5 h70
  text "A" at 14383.5,6893.5 h70
  text "B" at -416.5,4513.5 h70
  text "B" at 14383.5,4513.5 h70
  text "C" at -416.5,2138.5 h70
  text "C" at 14383.5,2138.5 h70
  text "PROJECT TITLE:" at 11343.5,277.5 h45
  text ".PRJ_Title" at 11393.5,144.17 h70
  text "DESIGNED FOR:" at 11343.5,-23.5 h45
  text ".PRJ_Customer" at 11393.5,-163.5 h70
  text "D" at -416.5,-231.5 h70
  text "D" at 14383.5,-231.5 h70
  text "FILE NAME:" at 11343.5,-323.5 h45
  text ".PCB_File_Name_No_Path" at 11393.5,-443.5 h70
  text "Texas Instruments (TI) and/or its licensors do not warrant the accuracy or completeness of this specification" at 6374,-605.34 h45
  text "ENGINEER:" at 11343.5,-613.5 h45
  text "LAYOUT BY:" at 12848.5,-613.5 h45
  text "or any information contained therein. TI and/or its licensors do not warrant that this design will meet" at 6329.01,-718 h45
  text ".PRJ_Engineer" at 11393.5,-768.49 h70
  text ".PCB_Layout" at 12899,-768.49 h70
  text "the specifications, will be suitable for your application or fit for any particular purpose, or will operate in" at 6329.01,-830.67 h45
  text "ALTIUM DESIGNER VERSION:" at 12848.5,-923.5 h45
  text "an implementation. TI and/or its licensors do not warrant that the design is production worthy. You should" at 6329.01,-943.33 h45
  text "completely validate and test your design implementation to confirm the system functionality for your application." at 6374,-1056 h45
  text ".print_Scale" at 11393.5,-1056.83 h70
  text ".Application_BuildNumber" at 12899,-1056.83 h70
  text "1" at 739.84,-1263.5 h70
  text "2" at 3235.5,-1263.5 h70
  text "3" at 5724.84,-1263.5 h70
  text "4" at 8231.51,-1263.5 h70
  text "5" at 10730.5,-1263.5 h70
  text "6" at 13235.5,-1263.5 h70
M10 Fab Notes:
  drawing of 185 lines, arcs and shapes, not listed
  text "DESIGN INFORMATION" at 12381.02,5910 h60
  text "MIN. TRACK WIDTH:" at 11736.46,5730 h60
  text "8" at 12832.7,5730 h60
  text "MIL" at 12987.46,5730 h60
  text "MIN. CLEARANCE:" at 11736.46,5598 h60
  text "0.2" at 12772.7,5598 h60
  text "mm" at 12987.46,5598 h60
  text "MIN. VIA PAD SIZE:" at 11736.46,5466 h60
  text "24" at 12802.71,5466 h60
  text "MIL" at 12987.46,5466 h60
  text "0.05mm (2MIL)" at 12431.46,5324.29 h60
  text "MINIMUM ANNULAR RING" at 11407.23,5320 h60
  text "EXTERNAL" at 13139.46,5320 h60
  text "PER" at 11607.23,5202 h60
  text "IPC-D-275 CLASS 2 LEVEL C" at 11827.23,5202 h60
  text "MIL, HOLES" at 13315.46,5089.71 h60
  text "+/-" at 12923,5089 h60
  text "+/-" at 13777,5089 h60
  text "REGISTRATION TOLERANCES:" at 11407.23,5084 h60
  text "METAL" at 12607,5084 h60
  text "5" at 13183.2,5084 h60
  text "3" at 14016.2,5084 h60
  text "MIL" at 14132.46,5084 h60
  text "MATERIAL:" at 11332.46,4874.54 h60
  text "FR-4 High Tg" at 12318.9,4734.21 h60
  text "FR-408" at 11753.46,4725.64 h60
  text "X" at 12165.46,4725.64 h60
  text "OTHER" at 13241.46,4725.64 h60
  text "62 MIL (1.6mm) +/-10%" at 12073.56,4562.92 h60
  text "THICKNESS:" at 11407.23,4558.64 h60
  text "X" at 11945.4,4558.64 h60
  text "OTHER" at 13358.46,4558.64 h60
  text "TOLERANCE:" at 11407.23,4400.64 h60
  text "X" at 12246.53,4400.64 h60
  text "ANSI IPC-6012 TYPE 3 CLASS 2" at 12433.48,4400.64 h60
  text "OTHER +/-" at 12433.46,4244.64 h60
  text "BOW & TWIST:" at 11407.23,4087.64 h60
  text "X" at 12246.53,4087.64 h60
  text "ANSI IPC-6012 TYPE 3 CLASS 2" at 12433.48,4087.64 h60
  text "OTHER +/-" at 12433.46,3929.13 h60
  text "DRILLING:" at 11332.46,3790.64 h60
  text "REFERENCE:" at 11407.23,3673.64 h60
  text "X" at 12055.46,3673.64 h60
  text "AS SHOWN" at 12242.46,3673.64 h60
  text "X" at 12956.46,3673.64 h60
  text "NC_DRILL FILES" at 13093.46,3673.64 h60
  text "PTH MIN COPPER THICKNESS:" at 11407.23,3515.64 h60
  text "X" at 12757.46,3515.64 h60
  text "1MIL" at 12894.46,3515.64 h60
  text "OTHER" at 13391.46,3515.64 h60
  text "BOARD FINISH:" at 11332.46,3356.64 h60
  text "SILKSCREEN:" at 11487.68,3238.64 h60
  text "X" at 12436.46,3238.64 h60
  text "TOP" at 12562.46,3238.64 h60
  text "X" at 12946.46,3238.64 h60
  text "BOTTOM" at 13073.46,3238.64 h60
  text "SILKSCREEN COLOR:" at 11487.68,3071.64 h60
  text "X" at 12435.42,3071.64 h60
  text "WHITE" at 12562.46,3071.64 h60
  text "OTHER" at 13073.46,3071.64 h60
  text "SOLDER RESIST COLOR:" at 11487.68,2901.64 h60
  text "X" at 12055.42,2742.44 h60
  text "GREEN" at 12182.46,2742.44 h60
  text "BLUE" at 12773.46,2742.44 h60
  text "OTHER" at 13311.46,2742.44 h60
  text "IMMERSION GOLD (ENIG)" at 12393.46,2553.92 h60
  text "ENEPIG" at 13731,2550.64 h60
  text "SURFACE FINISH:" at 11332.46,2549.64 h60
  text "X" at 12206.51,2549.64 h60
  text "IMM. TIN/SILVER OR EQUIV" at 11662,2392.64 h60
  text "OTHER" at 13093.46,2392.64 h60
  text "ARRAY/PANEL:" at 11332.46,2213.64 h60
  text "CUT AND TRIM PER MECH LAYER 1" at 12393.46,2209.35 h60
  text "N.C. ROUTE" at 12393.46,2057.64 h60
  text "X" at 13072.46,2057.64 h60
  text "V. SCORE" at 13259.46,2057.64 h60
  text "CERTIFICATION:" at 11332.46,1920.64 h60
  text "MATERIALS AND WORKMANSHIP FOR ALL PCBS" at 12057.46,1920.64 h60
  text "TO MEET OR EXCEED THE REQUIREMENTS OF:" at 12057.46,1822.64 h60
  text "X" at 11683.96,1686.13 h60
  text "ANSI IPC-A-600F CLASS ->" at 11822.96,1686.13 h60
  text "X" at 13462.02,1686.13 h60
  text "2" at 13580.96,1686.14 h60
  text "1" at 13265.96,1684.64 h60
  text "3" at 13934.96,1684.64 h60
  text "X" at 11686.02,1526.64 h60
  text "UL 94V-0" at 11822.96,1526.64 h60
  text "X" at 12498.02,1526.64 h60
  text "RoHS" at 12634.96,1526.64 h60
  text "OTHER" at 13279.36,1526.64 h60
  text "PER ORDER" at 13676.42,1526.64 h60
  text "ADDITIONAL REQUIREMENTS:" at 11332.46,1385.64 h60
  text "MICROSECTION:" at 11407.23,1270.64 h60
  text "YES" at 12312.96,1270.64 h60
  text "REQUIRED" at 13174.46,1114.49 h60
  text "BARE BOARD ELEC. TEST:" at 11407.23,1111.64 h60
  text "NONE" at 12712.96,1111.64 h60
  text "X" at 13047.46,1111.64 h60
  text "PER ORDER" at 13766.46,1111.64 h60
  text "MANUFACTURER'S UL:" at 11407.23,954.64 h60
  text "RAIL" at 12572.96,950.35 h60
  text "METAL" at 13064.77,950.35 h60
  text "X" at 13440,950 h60
  text "SILK" at 13576.46,950.35 h60
M12 Stackup:
  drawing of 191 lines, arcs and shapes, not listed
  text "Layer" at 9790.34,7830 h60
  text "Name" at 10200.26,7830 h60
  text "Material" at 11130,7830 h60
  text "Thickness" at 11989.77,7830 h60
  text "Constant" at 12639.6,7830 h60
  text "Board Layer Stack" at 13209.46,7830 h60
  text "1" at 9790.34,7710 h60
  text "Top Overlay" at 10200.26,7710 h60
  text "2" at 9790.34,7590 h60
  text "Top Solder" at 10200.26,7590 h60
  text "Solder Resist" at 11130,7590 h60
  text "0.40mil" at 11989.77,7590 h60
  text "3.5" at 12639.6,7590 h60
  text "3" at 9790.34,7470 h60
  text "Top Layer" at 10200.26,7470 h60
  text "Copper" at 11130,7470 h60
  text "1.40mil" at 11989.77,7470 h60
  text "4" at 9790.34,7350 h60
  text "Dielectric1" at 10200.26,7350 h60
  text "FR-4" at 11130,7350 h60
  text "59.20mil" at 11989.77,7350 h60
  text "4.8" at 12639.6,7350 h60
  text "5" at 9790.34,7230 h60
  text "Bottom Layer" at 10200.26,7230 h60
  text "Copper" at 11130,7230 h60
  text "1.40mil" at 11989.77,7230 h60
  text "6" at 9790.34,7110 h60
  text "Bottom Solder" at 10200.26,7110 h60
  text "Solder Resist" at 11130,7110 h60
  text "0.40mil" at 11989.77,7110 h60
  text "3.5" at 12639.6,7110 h60
  text "7" at 9790.34,6990 h60
  text "Bottom Overlay" at 10200.26,6990 h60

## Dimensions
2500,2500 to 2500,0 on M2 Board Dimensions
0,2500 to 2500,2500 on M2 Board Dimensions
